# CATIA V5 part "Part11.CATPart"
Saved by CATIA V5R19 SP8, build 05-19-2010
Part number: Arbre d'entrée
Bounding box of the stored display mesh (mm): x 0 to 300, y -10 to 10, z -10 to 10
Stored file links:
  F:\CFAO\Hberriche\Part11.CATPart
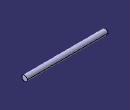
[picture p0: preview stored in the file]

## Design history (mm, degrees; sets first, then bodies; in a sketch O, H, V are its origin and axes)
Body1 (main body)
  Sketch1 on yz-plane, origin (0, 0, 0), H (0, 1, 0), V (0, 0, 1)
    circle A1 centre (0, 0) radius 10
    radius A1 = 10
  Pad1: profile Sketch1, direction (1, 0, 0), length 300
